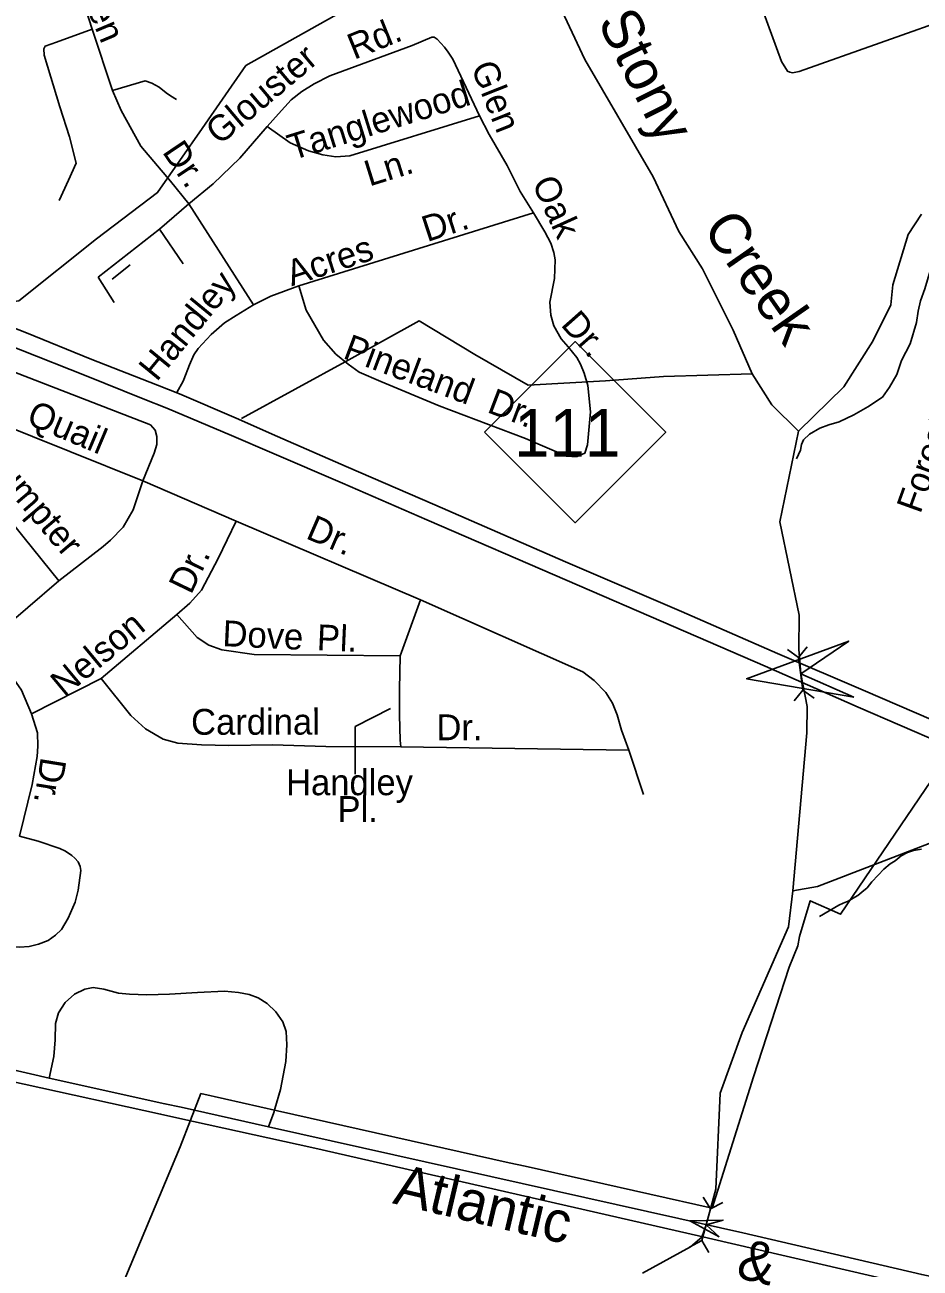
# Model space of a CAD drawing. Extents: x 2260773 to 2342389, y 552869 to 618546.
# Drawn here: x 2309150 to 2312438, y 596680 to 601248 of the extents above; entities that cross this region are included whole.
import ezdxf

# ---------------------------------------------------------------- set-up
doc = ezdxf.new("R2010")
doc.units = 0
for name, color, linetype in [('Exist Boundary Political City Limit New', 7, 'Continuous'), ('Exist Hydrographic Creek Single Shore', 7, 'Continuous'), ('Exist Hydrographic Creek Single Shore Label', 7, 'Continuous'), ('Exist Hydrographic Misc Water Feature', 7, 'Continuous'), ('Exist Railroad Mainline', 7, 'Continuous'), ('Exist Railroad Mainline Label', 7, 'Continuous'), ('Exist Road Non-System Type 51', 7, 'Continuous'), ('Exist Road Non-System Type 51 Label', 7, 'Continuous'), ('Exist Road Primary NC Shield CELL', 7, 'Continuous'), ('Exist Road Primary NC Shield Number Label', 7, 'Continuous'), ('Exist Road Primary US Divided Attributed', 7, 'Continuous'), ('Exist Road Primary US Service Attributed', 7, 'Continuous'), ('Exist Road Secondary Structure Culvert Attributed CELL', 7, 'Continuous'), ('Exist Road Secondary Structure Culvert CELL', 7, 'Continuous'), ('Exist Road Secondary Structure Standard Bridge Attributed CELL', 7, 'Continuous'), ('Exist Road Secondary Type 51 Attributed', 7, 'Continuous'), ('Map Preparation Boundary City Limit Buffer Line', 7, 'Continuous')]:
    doc.layers.add(name, color=color, linetype=linetype)

msp = doc.modelspace()

# ---------------------------------------------------------------- linework, layer by layer
at = {"layer": 'Exist Boundary Political City Limit New'}
msp.add_lwpolyline([(2309407, 596377.8), (2309719.5, 597126.3), (2309796, 597321.3), (2309882.2, 597302), (2310078, 597258.1), (2310928.8, 597067.5), (2310986.5, 597054.6), (2311674, 596900.6), (2311825.5, 597382.6), (2311956.2, 597785.6), (2311988.8, 597864.2), (2311995, 597898.1), (2312034.2, 598030), (2312145.5, 597980.4), (2312500, 598504)], dxfattribs=at)
at = {"layer": 'Exist Hydrographic Creek Single Shore'}
for points in [[(2311990.9, 599754.9), (2311893.3, 599852.6), (2311820.6, 599965.6), (2311751.1, 600126.2), (2311638.5, 600351.5), (2311550.9, 600489.2), (2311457.1, 600689.5), (2311206.8, 601121.4), (2311112.6, 601319.4), (2311078.4, 601357), (2311044.3, 601418.4), (2310928.3, 601640.4), (2310881.2, 601703.9), (2310839.2, 601735)], [(2311990.9, 599754.9), (2312158.1, 599917.9), (2312264.1, 600086.2), (2312330.1, 600220.1), (2312337.1, 600292.6), (2312394.1, 600478.7), (2312443.1, 600552.9)], [(2311970.2, 598065.9), (2312022.2, 598646.5), (2312023.3, 598743.8), (2311999.3, 598863.9), (2311992.5, 598954.3), (2311993.6, 599079), (2311922.3, 599422.6), (2311990.9, 599754.9)], [(2311418.2, 596662.1), (2311594.6, 596758.1), (2311635.7, 596793.6), (2311651.7, 596839.4), (2311687.2, 596969.8), (2311703.3, 597323.4), (2311784.3, 597546.5), (2311954.2, 597934.1), (2311970.2, 598065.9)]]:
    msp.add_lwpolyline(points, dxfattribs=at)
at = {"layer": 'Exist Hydrographic Misc Water Feature'}
for points in [[(2308855.1, 600275.9), (2309019.5, 600219.5), (2309127.4, 600234.9), (2309413, 600461.7), (2309636.9, 600632.3), (2309800.6, 600867.6), (2309961.5, 601099.3), (2310365.2, 601326.2), (2310631.4, 601473.1), (2310730.3, 601524.3), (2310836.1, 601589.2), (2310877.1, 601613.1), (2310928.3, 601640.4)], [(2312540.9, 600471.3), (2312529.2, 600457.2), (2312496, 600405.1), (2312474.5, 600344.7), (2312455.4, 600278.6), (2312439.4, 600234.4), (2312430.2, 600196.4), (2312424.4, 600154.3), (2312401.7, 600076.2), (2312369.9, 600015.7), (2312352.7, 599963.5), (2312325.2, 599917.4), (2312300, 599881), (2312245.8, 599844.5), (2312194.4, 599815.8), (2312140.6, 599789.4), (2312102.7, 599778.9), (2312068.9, 599766.6), (2312031.1, 599744.3), (2312009.4, 599724), (2312001.8, 599706.1), (2311997.9, 599686), (2311984.2, 599654)], [(2309945.3, 599802), (2310339.3, 600018), (2310597.4, 600160.4), (2310802.7, 600037.1), (2310997.9, 599925), (2311281.7, 599940.3), (2311495.1, 599956.4), (2311820.6, 599965.6)], [(2317861.2, 597021.1), (2317660.2, 597118), (2317276.2, 597240.2), (2316850.3, 597367.4), (2316356.3, 597564.1), (2316038.3, 597708.7), (2315488.3, 597778.3), (2315378.2, 597846.1), (2315193.2, 598015.8), (2314991.3, 598257.1), (2314898.2, 598397.7), (2314746.2, 598578.6), (2314612.1, 598678.2), (2314253.3, 598765.4), (2314019.1, 598762.5), (2313355.2, 598581.4), (2312061.1, 598082.8), (2311970.2, 598065.9)], [(2312442.9, 598219.5), (2312413.4, 598215.1), (2312391.6, 598207), (2312367.8, 598194.8), (2312346.1, 598176.5), (2312327.8, 598166.3), (2312304.5, 598145.9), (2312284.2, 598123.8), (2312260.6, 598099.8), (2312243, 598077.3), (2312223.3, 598061.2), (2312209.3, 598049.1), (2312197.6, 598043.2), (2312173.6, 598028.9), (2312155.6, 598020.7), (2312139.6, 598014.2), (2312068.5, 597971.8)]]:
    msp.add_lwpolyline(points, dxfattribs=at)
at = {"layer": 'Exist Railroad Mainline'}
msp.add_lwpolyline([(2304294.9, 598418.8), (2304538, 598363.6), (2304748.3, 598321.9), (2304960.9, 598270.3), (2305950.6, 598053.5), (2306429.5, 597948.6), (2306491.6, 597935), (2306716.2, 597886.4), (2307180.2, 597785.8), (2308144.5, 597577), (2309648, 597246.1), (2309708.2, 597232.8), (2310214.4, 597121.4), (2311623.2, 596798.7), (2311745.3, 596770.1), (2313214.2, 596430), (2313294.1, 596411.6), (2313449.1, 596375.8)], dxfattribs=at)
at = {"layer": 'Exist Road Non-System Type 51'}
for p, q in [((2309471, 601007.5), (2309396.1, 601232.5)), ((2309752, 600590.2), (2309644, 600498.1)), ((2309989.3, 600219.1), (2309752, 600590.2)), ((2311018, 600557.5), (2310155.7, 600289.9)), ((2309644, 600498.1), (2309419.2, 600320.9)), ((2309644, 600498.1), (2309730.8, 600370.5)), ((2309535.7, 600367), (2309470.2, 600313.8)), ((2309419.2, 600320.9), (2309477.3, 600228)), ((2309583.1, 599572.5), (2309000.2, 599806.4)), ((2309583.1, 599572.5), (2309925, 599424.5)), ((2309925, 599424.5), (2310603.2, 599136.1)), ((2309002.8, 598972.9), (2309273.8, 599205.3)), ((2310603.2, 599136.1), (2310528.2, 598930.5)), ((2309429.4, 598846.8), (2309707.9, 599081.4)), ((2309174.1, 598717.1), (2309429.4, 598846.8)), ((2311368.1, 598583.1), (2310530.2, 598596)), ((2311368.1, 598583.1), (2311421.5, 598420.1)), ((2310064.6, 597255.1), (2310067.6, 597265.2))]:
    msp.add_line(p, q, dxfattribs=at)
for points in [[(2312693.2, 601623), (2312764.7, 601410.4), (2312772.6, 601382.6), (2312776.6, 601362.7), (2312768.6, 601346.8), (2312697.2, 601320.9), (2312587.9, 601287.2), (2311993, 601076.6), (2311968.9, 601072.4), (2311958.9, 601074.2), (2311950.9, 601078.1), (2311928.4, 601113.8), (2311860.4, 601301.1)], [(2309396.1, 601232.5), (2309357.2, 601354.8), (2309316.5, 601477)], [(2309396.1, 601232.5), (2309265.1, 601184.7), (2309224.4, 601170.5), (2309219.1, 601159.9), (2309220.9, 601136.8), (2309277.5, 600947.3), (2309312.9, 600837.4), (2309337.7, 600740), (2309309.4, 600677.9), (2309275.7, 600603.5)], [(2310819.7, 600914.5), (2310721, 601122.9), (2310704.7, 601148.7), (2310690.6, 601166.5), (2310663.9, 601196.2), (2310653.4, 601202.6), (2310650.4, 601203.8), (2310644.4, 601203.3), (2310571.8, 601173.2), (2310269.1, 601061.5), (2310212.4, 601031.4), (2310166.4, 601003.1), (2310127.4, 600972.9), (2310081.6, 600922), (2310038.9, 600875.5)], [(2309706, 600973.8), (2309684.8, 600988), (2309668.8, 600998.6), (2309642.3, 601019.9), (2309615.7, 601034.1), (2309590.9, 601042.9), (2309471, 601007.5)], [(2309752, 600590.2), (2309684.8, 600673.5), (2309575.1, 600802.7), (2309503.8, 600933.8), (2309471, 601007.5)], [(2310819.7, 600914.5), (2310343.4, 600767.4), (2310292.1, 600763.9), (2310244.3, 600771), (2310191.2, 600785.1), (2310123.9, 600815.3), (2310038.9, 600875.5)], [(2311018, 600557.5), (2310968.5, 600636.3), (2310920.7, 600732), (2310855.1, 600845.4), (2310819.7, 600914.5)], [(2310038.9, 600875.5), (2309939.4, 600758.6), (2309840.6, 600664.7), (2309752, 600590.2)], [(2311018, 600557.5), (2311058.8, 600488.4), (2311081.8, 600445.8), (2311092.4, 600412.2), (2311097.7, 600385.6), (2311094.2, 600316.5), (2311078.2, 600229.7), (2311081.8, 600181.9), (2311092.4, 600142.9), (2311119, 600095), (2311145.5, 600064.9), (2311177.4, 600025.9), (2311189.8, 600001.1), (2311203.2, 599968.6), (2311217.7, 599922.7), (2311226.7, 599826.9), (2311216.1, 599705), (2311206.3, 599674.8), (2311178.6, 599662.5), (2311158.6, 599662.3), (2311138.5, 599664.1), (2310987.9, 599728.3), (2310671, 599848.8), (2310456.8, 599937.4), (2310377.1, 599972.8), (2310336.4, 600001.1), (2310292.1, 600038.3), (2310246, 600089.7), (2310182.3, 600199.6), (2310155.7, 600289.9)], [(2310155.7, 600289.9), (2310053, 600251), (2309989.3, 600219.1)], [(2309989.3, 600219.1), (2309925.6, 600180.1), (2309883.1, 600153.5), (2309833.5, 600111), (2309785.7, 600059.6), (2309770.3, 600036.2), (2309753.8, 599999.4), (2309733.4, 599945.7)], [(2309733.4, 599945.7), (2309730.8, 599939.1), (2309707.7, 599897.1)], [(2309000.2, 599806.4), (2308981.2, 599745.5), (2308971.5, 599689.6), (2308970, 599657.7), (2308974.9, 599621), (2308986.5, 599587), (2309004.8, 599545.6), (2309029.8, 599509.1), (2309147, 599363), (2309273.8, 599205.3)], [(2309273.8, 599205.3), (2309437.1, 599332.2), (2309464, 599355.3), (2309510.1, 599403.3), (2309547.5, 599467), (2309583.1, 599572.5)], [(2309707.9, 599081.4), (2309756, 599123.6), (2309798.2, 599170.7), (2309859.7, 599288), (2309925, 599424.5)], [(2311368.1, 598583.1), (2311341.3, 598656.8), (2311325.5, 598713.2), (2311308.2, 598756.5), (2311283.2, 598794.9), (2311241, 598839.1), (2311198.7, 598871.8), (2310603.2, 599136.1)], [(2310528.2, 598930.5), (2309992.3, 598934.3), (2309873.1, 598951.6), (2309825.1, 598968.9), (2309782.9, 598997.7), (2309707.9, 599081.4)], [(2309174.1, 598717.1), (2309137.3, 598803.4), (2309100.5, 598856.8), (2309002.8, 598972.9)], [(2310528.2, 598930.5), (2310526.1, 598805.9), (2310525.1, 598712), (2310528, 598620.1), (2310530.2, 598596)], [(2310530.2, 598596), (2310255.4, 598596.9), (2310059.5, 598602.7), (2309898.1, 598600.8), (2309798.2, 598602.7), (2309711.8, 598608.5), (2309658, 598623.8), (2309592.7, 598662.3), (2309538.9, 598710.4), (2309429.4, 598846.8)], [(2309129.6, 598267.7), (2309176.5, 598457.6), (2309194.4, 598559.7), (2309196.9, 598597.8), (2309195.6, 598647.3), (2309174.1, 598717.1)], [(2309028.1, 597877.9), (2309053.5, 597868.2), (2309084, 597862.7), (2309129.6, 597858.9), (2309165.2, 597861.4), (2309199.4, 597870.3), (2309235, 597884.3), (2309261.6, 597903.3), (2309284.4, 597924.9), (2309308.5, 597965.5), (2309333.9, 598025.2), (2309345.3, 598068.4), (2309354.6, 598140.7), (2309352.9, 598156), (2309345.3, 598172.5), (2309333.5, 598186.4), (2309322.5, 598196.6), (2309298.8, 598212.7), (2309278.1, 598222), (2309198.2, 598248.6), (2309129.6, 598267.7)], [(2310067.6, 597265.2), (2310088.8, 597336.5), (2310107.9, 597439.3), (2310111.7, 597500.2), (2310109.1, 597549.7), (2310096.4, 597585.3), (2310071.1, 597622.1), (2310039.3, 597652.6), (2310006.4, 597672.9), (2309973.4, 597685.6), (2309934, 597693.2), (2309883.3, 597698.3), (2309783.1, 597693.2), (2309680.3, 597686.9), (2309597.8, 597684.3), (2309534.4, 597686.9), (2309493.8, 597690.7), (2309439.2, 597704.6), (2309399.9, 597711), (2309369.4, 597704.6), (2309331.4, 597686.9), (2309297.1, 597656.4), (2309273, 597618.3), (2309261.6, 597578.9), (2309260.3, 597519.3), (2309256.5, 597458.3), (2309238.8, 597378.3)], [(2310044.4, 597199.3), (2310063.5, 597251.4), (2310064.6, 597255.1)]]:
    msp.add_lwpolyline(points, dxfattribs=at)
at = {"layer": 'Exist Road Non-System Type 51 Label'}
msp.add_lwpolyline([(2310363.2, 598495.6), (2310363.2, 598670.3), (2310492.2, 598736.1)], dxfattribs=at)
at = {"layer": 'Exist Road Primary NC Shield CELL'}
msp.add_lwpolyline([(2310837.2, 599751.8), (2311170.2, 600084.8), (2311503.2, 599751.8), (2311170.2, 599418.8)], close=True, dxfattribs=at)
at = {"layer": 'Exist Road Primary US Divided Attributed'}
for points in [[(2308136.8, 600455.4), (2308371.3, 600362.3), (2308714.9, 600224.2), (2308995.5, 600109.5), (2309095.3, 600069.6), (2309133.6, 600054.6), (2309374.4, 599958.7), (2309584.6, 599874.3), (2309670.4, 599840.5), (2309908.2, 599739.2), (2310056.9, 599676.3), (2310316.2, 599564.3), (2310626, 599429.2), (2311141.3, 599206.7), (2311532.4, 599037.9), (2311869, 598891.7), (2312210.1, 598740.9), (2312516.2, 598608.8)], [(2313958.7, 598054.9), (2313837.5, 598108.5), (2313593.3, 598213.7), (2313247.5, 598362.2), (2313011.5, 598463.9), (2312816.4, 598549.2), (2312669.2, 598613.5), (2312540.7, 598669.6), (2312237, 598800.5), (2311913.4, 598938.4), (2311561.6, 599093.1), (2311135.2, 599275.7), (2310655.1, 599484.4), (2310330, 599625.6), (2310076.9, 599736.1), (2309925, 599803.7), (2309718, 599892.7), (2309636.7, 599924.9), (2309389.9, 600021.3), (2309155.2, 600116.2), (2309077.7, 600147.5)]]:
    msp.add_lwpolyline(points, dxfattribs=at)
at = {"layer": 'Exist Road Primary US Service Attributed'}
msp.add_lwpolyline([(2306887.2, 600412.8), (2306946.6, 600328.9), (2307016, 600275.4), (2307053.6, 600265.4), (2307093.2, 600263.5), (2307208.1, 600279.3), (2307788.4, 600400.2), (2307931, 600413.1), (2307980.5, 600409.1), (2308216.2, 600333.8), (2308473.6, 600238.7), (2309012.3, 600010.8), (2309610.5, 599778.9), (2309628.3, 599759.1), (2309634.2, 599735.3), (2309634.2, 599706.6), (2309624.3, 599674.9), (2309583.1, 599572.5)], dxfattribs=at)
at = {"layer": 'Exist Road Secondary Structure Culvert Attributed CELL'}
msp.add_lwpolyline([(2312194.5, 598778), (2311800.2, 598845.5), (2312175.3, 598984.2), (2311999.3, 598863.9)], close=True, dxfattribs=at)
at = {"layer": 'Exist Road Secondary Structure Culvert CELL'}
for p, q in [((2311950.3, 598953.7), (2311991.4, 598923.9)), ((2312023.4, 598963.3), (2311991.4, 598923.9)), ((2311991.4, 598923.9), (2312007.2, 598804)), ((2311975.2, 598764.6), (2312007.2, 598804)), ((2312048.3, 598774.2), (2312007.2, 598804)), ((2311641.4, 596941.1), (2311667.7, 596897.7)), ((2311635.7, 596781.1), (2311667.7, 596897.7)), ((2311712.5, 596921.6), (2311667.7, 596897.7)), ((2311590.9, 596757.1), (2311635.7, 596781.1)), ((2311662, 596737.6), (2311635.7, 596781.1))]:
    msp.add_line(p, q, dxfattribs=at)
at = {"layer": 'Exist Road Secondary Structure Standard Bridge Attributed CELL'}
msp.add_lwpolyline([(2311699.7, 596795.5), (2311592.4, 596853.5), (2311714.3, 596856.9), (2311651.7, 596839.4)], close=True, dxfattribs=at)
at = {"layer": 'Exist Road Secondary Type 51 Attributed'}
for points in [[(2311551.8, 596862.6), (2310044.4, 597199.3), (2309723.4, 597271.2), (2309663.7, 597284.4), (2309238.8, 597378.3), (2308915.2, 597453.3), (2308478.8, 597544), (2307864.7, 597677.3), (2307192.2, 597843.6), (2306732.9, 597942), (2306452.5, 598005.5), (2305971.7, 598107.1), (2304888.1, 598347.7), (2304346.9, 598464.1)], [(2313453.6, 596444.6), (2313441.9, 596447.2), (2313409.2, 596454.7), (2313281.5, 596479.7), (2313269.6, 596482), (2312443.7, 596656.6), (2311786.4, 596810.2), (2311551.8, 596862.6)]]:
    msp.add_lwpolyline(points, dxfattribs=at)
at = {"layer": 'Map Preparation Boundary City Limit Buffer Line'}
msp.add_lwpolyline([(2309407, 596377.8), (2309719.5, 597126.3), (2309796, 597321.3), (2309882.2, 597302), (2310078, 597258.1), (2310928.8, 597067.5), (2310986.5, 597054.6), (2311674, 596900.6), (2311825.5, 597382.6), (2311956.2, 597785.6), (2311988.8, 597864.2), (2311995, 597898.1), (2312034.2, 598030), (2312145.5, 597980.4), (2312500, 598504)], dxfattribs=at)

# ---------------------------------------------------------------- texts
at = {"layer": 'Exist Hydrographic Creek Single Shore Label'}
for s, rotation, p in [('Stony', 296.7288, (2311251.1, 601260.1)), ('Creek', 304.8944, (2311635.8, 600500))]:
    msp.add_text(s, height=150, rotation=rotation, dxfattribs=at).set_placement(p)
at = {"layer": 'Exist Railroad Mainline Label'}
for s, rotation, p in [('Atlantic', 346.7203, (2310497.2, 596918.8)), ('&', 346.7039, (2311757.4, 596646.5))]:
    msp.add_text(s, height=150, rotation=rotation, dxfattribs=at).set_placement(p)
at = {"layer": 'Exist Road Non-System Type 51 Label'}
for s, rotation, p in [('Loch  -aven', 292.8702, (2309174.6, 601786.7)), ('Rd.', 22.0378, (2310359, 601119.5)), ('Glouster', 40.0769, (2309864.4, 600803.6)), ('Glen', 291.6236, (2310786.8, 601093.7)), ('Tanglewood', 17.3356, (2310132.3, 600750)), ('Dr.', 303.995, (2309651.9, 600781.5)), ('Ln.', 17.3356, (2310414.9, 600654.1)), ('Oak', 294.4883, (2311010.5, 600667.8)), ('Dr.', 18.1028, (2310626.8, 600449.9)), ('Acres', 18.1028, (2310129.2, 600287.3)), ('Handley', 50.6213, (2309633.7, 599934.6)), ('Dr.', 311.5198, (2311114.7, 600145.3)), ('Pineland', 339.4824, (2310313.8, 600024.8)), ('Dr.', 339.1541, (2310843.3, 599826.4)), ('Quail', 337.1154, (2309150.8, 599784)), ('Forest', 70.2382, (2312438.2, 599448.9)), ('Sumpter', 310.3786, (2308986.4, 599652.4)), ('Dr.', 336.6909, (2310177.4, 599363.2)), ('Dr.', 64.2476, (2309759.7, 599152.1)), ('Nelson', 39.6762, (2309294.2, 598775.7)), ('Dove', 357.2787, (2309873.7, 598965.9)), ('Pl.', 357.4183, (2310220.5, 598950.9)), ('Cardinal', 0.0876, (2309760, 598639.8)), ('Dr.', 0.0684, (2310661.2, 598619.9)), ('Dr.', 260.8665, (2309208.7, 598560.6)), ('Handley', 0.0139, (2310108.7, 598417.8)), ('Pl.', 0.0171, (2310297.8, 598319.4))]:
    msp.add_text(s, height=95, rotation=rotation, dxfattribs=at).set_placement(p)
at = {"layer": 'Exist Road Primary NC Shield Number Label'}
msp.add_text('111', height=175, dxfattribs=at).set_placement((2310946.3, 599662))

doc.saveas('drawing.dxf')
